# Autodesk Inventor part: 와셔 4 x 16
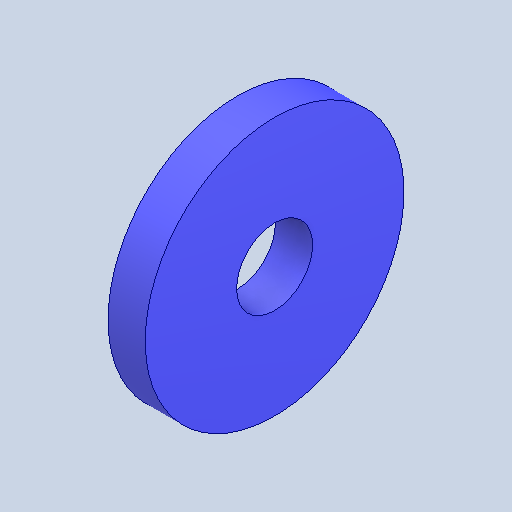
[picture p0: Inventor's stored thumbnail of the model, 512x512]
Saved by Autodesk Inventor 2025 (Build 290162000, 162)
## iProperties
Created: 2024-07
Part Number: 와셔 4 x 16
Material: 강철, 연강
Description: 미터법 평면 와셔
Document SubType Name: Modeling
Designer: hsj03
Density: 7.85 g/cm^3
Appearance: 기본값
Author: jhkim
Sending System: Autodesk Inventor 2025
Preprocessor: ST-DEVELOPER v20
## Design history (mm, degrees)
feature "Solid1"
node "솔리드1"
